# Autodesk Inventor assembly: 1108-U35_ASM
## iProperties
Created: 2007-03
Part Number: 1108-U35_ASM
Document SubType Name: Assembly
Designer: Andy Moles
Mass: 2.38764 g
Surface Area: 34.5846 cm^2
Volume: 2.2776 cm^3
Density: 1.04831 g/cm^3
Author: Andy Moles
